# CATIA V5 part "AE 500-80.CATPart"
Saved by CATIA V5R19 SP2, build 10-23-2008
Part number: AE 500-80
Bounding box of the stored display mesh (mm): x -22.494 to 22.494, y -22.494 to 22.494, z 0 to 210
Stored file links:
  C:\Users\Bora\Desktop\3D Katı model\AE serisi\AE 500\AE 500-80.CATPart
  C:\Program Files\Dassault Systemes\B19\intel_a\reffiles\standard\MetricThickPitch.txt
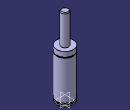
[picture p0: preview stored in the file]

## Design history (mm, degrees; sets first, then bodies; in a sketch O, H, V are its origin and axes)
Body1 (main body)
  Sketch1 on yz-plane, origin (0, 0, 0), H (0, 1, 0), V (0, 0, 1)
    point P1 (22.5, 113.5)
    point P8 (22.5, 115.5)
    point P9 (22.5, 115.5)
    point P10 (22.5, 113.5)
    point P11 (10, 208)
    point P13 (10, 208)
    line L1 (22.5, 113.5) -> (22.5, 8)
    line L2 (22.5, 4) -> (22.5, 0)
    line L3 (20, 8) -> (20, 4)
    line L4 (22.5, 129) -> (22.5, 115.5)
    arc A1 centre (22.5, 114.5) radius 1 from (22.5, 115.5) to (22.5, 113.5) ccw
    line L5 (10, 208) -> (10, 129)
    arc A2 centre (8, 208) radius 2 from (10, 208) to (8, 210) ccw
    line L6 (8, 210) -> (0, 210)
    point P15 (0, 210)
    line L7 (10, 129) -> (22.5, 129)
    line L8 (20, 8) -> (22.5, 8)
    line L9 (20, 4) -> (22.5, 4)
    line L10 (22.5, 0) -> (0, 0)
    coincidence: P15 V, P1 P10, P8 P9, P11 P13
    tangency: L6 A2
    horizontal: L7 H, L8 H, L9 H, L10 H
  Shaft1: profile Sketch1, axis Sketch1.V, angle 360
  Sketch2 on face of Shaft1 from Sketch1.L10, origin (0, 0, 0), H (1, 0, 0), V (0, -1, 0)
    point P1 (10, 0)
    distance P1 V = 10
  Hole1: placed by Sketch2, at (10, 0, 0) direction (0, 0, 1), diameter 6.647, depth 13, threaded "M8", thread diameter 8, thread depth 13, pitch 1.25
  CircPattern1: of Hole1, instances 2, angular step 180, axis from xy-plane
